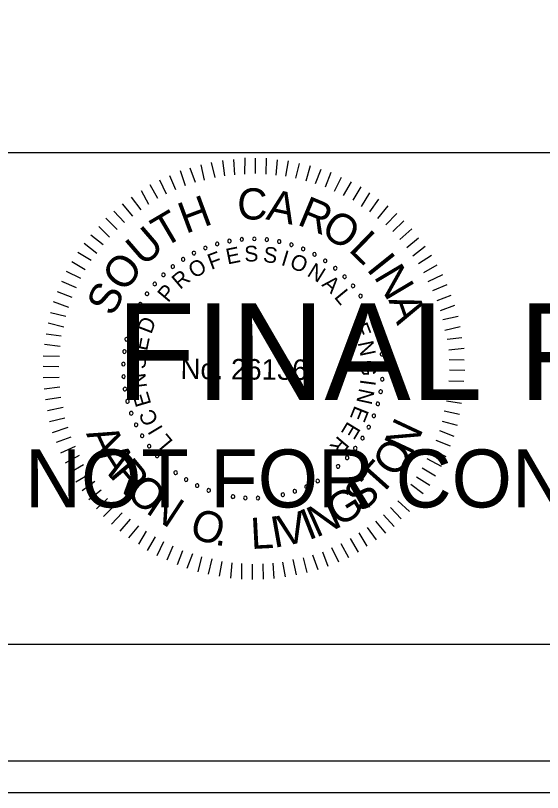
# Model space of a CAD drawing. Extents: x 967 to 1326, y 964 to 1744.
# Drawn here: x 1170.56 to 1189.3, y 1243.72 to 1271.36 of the extents above; entities that cross this region are included whole.
import ezdxf

# ---------------------------------------------------------------- set-up
doc = ezdxf.new("R2010")
doc.units = 0
for name, color, linetype in [('RD_PD_PaveShd', 7, 'Continuous'), ('RD_XS_Base', 7, 'Continuous'), ('RD_XS_CurbBase', 7, 'Continuous'), ('RD_XS_TieSlope', 7, 'Continuous'), ('RD_XS_TX_TOC', 7, 'Continuous')]:
    doc.layers.add(name, color=color, linetype=linetype)

msp = doc.modelspace()

# ---------------------------------------------------------------- linework, layer by layer
at = {"layer": 'RD_PD_PaveShd'}
for p, q in [((996.114, 1266.486), (1323.886, 1266.486)), ((1323.886, 1248.983), (996.114, 1248.983))]:
    msp.add_line(p, q, dxfattribs=at)
at = {"layer": 'RD_XS_CurbBase'}
msp.add_lwpolyline([(967.409, 1243.72), (1326.285, 1243.72), (1326.285, 1463.72), (967.409, 1463.72)], close=True, dxfattribs=at)
at = {"layer": 'RD_XS_TieSlope'}
for p, q in [((1178.01, 1265.663), (1177.93, 1266.209)), ((1178.364, 1265.699), (1178.33, 1266.244)), ((1178.717, 1265.719), (1178.722, 1266.295)), ((1179.093, 1265.739), (1179.098, 1266.292)), ((1179.469, 1265.713), (1179.489, 1266.288)), ((1179.829, 1265.687), (1179.872, 1266.231)), ((1180.174, 1265.646), (1180.271, 1266.19)), ((1176.964, 1265.419), (1176.769, 1265.935)), ((1177.287, 1265.508), (1177.169, 1266.054)), ((1177.657, 1265.597), (1177.53, 1266.128)), ((1180.535, 1265.573), (1180.662, 1266.102)), ((1180.902, 1265.478), (1181.045, 1266.022)), ((1176.264, 1265.156), (1176.053, 1265.657)), ((1176.61, 1265.306), (1176.423, 1265.83)), ((1181.231, 1265.384), (1181.428, 1265.896)), ((1181.584, 1265.265), (1181.78, 1265.786)), ((1175.933, 1265.005), (1175.699, 1265.506)), ((1181.905, 1265.109), (1182.154, 1265.606)), ((1182.226, 1264.953), (1182.506, 1265.45)), ((1175.308, 1264.634), (1175.036, 1265.12)), ((1175.624, 1264.846), (1175.352, 1265.332)), ((1182.562, 1264.789), (1182.85, 1265.27)), ((1175.03, 1264.445), (1174.681, 1264.9)), ((1182.86, 1264.572), (1183.163, 1265.053)), ((1183.158, 1264.378), (1183.484, 1264.828)), ((1174.729, 1264.217), (1174.372, 1264.665)), ((1183.447, 1264.145), (1183.811, 1264.587)), ((1174.435, 1263.997), (1174.062, 1264.399)), ((1183.729, 1263.92), (1184.116, 1264.316)), ((1174.172, 1263.753), (1173.776, 1264.148)), ((1183.98, 1263.672), (1184.368, 1264.061)), ((1173.909, 1263.479), (1173.52, 1263.858)), ((1184.232, 1263.394), (1184.657, 1263.767)), ((1173.684, 1263.197), (1173.242, 1263.546)), ((1184.475, 1263.108), (1184.892, 1263.45)), ((1173.451, 1262.9), (1173.009, 1263.256)), ((1184.687, 1262.807), (1185.128, 1263.156)), ((1173.257, 1262.64), (1172.776, 1262.936)), ((1173.039, 1262.312), (1172.559, 1262.6)), ((1184.885, 1262.544), (1185.355, 1262.832)), ((1185.081, 1262.213), (1185.56, 1262.493)), ((1172.883, 1262.006), (1172.379, 1262.256)), ((1185.24, 1261.904), (1185.756, 1262.145)), ((1172.727, 1261.677), (1172.215, 1261.904)), ((1185.399, 1261.573), (1185.907, 1261.791)), ((1172.571, 1261.333), (1172.051, 1261.53)), ((1185.549, 1261.226), (1186.057, 1261.414)), ((1172.461, 1260.974), (1171.91, 1261.178)), ((1185.669, 1260.865), (1186.185, 1261.06)), ((1172.351, 1260.652), (1171.807, 1260.787)), ((1185.759, 1260.541), (1186.297, 1260.667)), ((1172.286, 1260.276), (1171.727, 1260.419)), ((1185.832, 1260.165), (1186.371, 1260.298)), ((1172.191, 1259.955), (1171.647, 1260.029)), ((1185.906, 1259.842), (1186.436, 1259.906)), ((1172.15, 1259.587), (1171.598, 1259.653)), ((1185.964, 1259.473), (1186.51, 1259.53)), ((1172.124, 1259.234), (1171.548, 1259.239)), ((1185.977, 1259.12), (1186.514, 1259.115)), ((1172.105, 1258.866), (1171.545, 1258.871)), ((1185.997, 1258.751), (1186.542, 1258.747)), ((1172.118, 1258.482), (1171.542, 1258.471)), ((1185.971, 1258.368), (1186.508, 1258.348)), ((1172.138, 1258.136), (1171.585, 1258.072)), ((1185.952, 1258.022), (1186.497, 1257.949)), ((1172.173, 1257.768), (1171.627, 1257.688)), ((1185.888, 1257.655), (1186.417, 1257.566)), ((1172.262, 1257.414), (1171.701, 1257.296)), ((1185.808, 1257.302), (1186.345, 1257.175)), ((1172.321, 1257.037), (1171.774, 1256.911)), ((1185.729, 1256.926), (1186.265, 1256.792)), ((1172.425, 1256.707), (1171.871, 1256.519)), ((1185.634, 1256.597), (1186.146, 1256.401)), ((1172.53, 1256.36), (1172.007, 1256.173)), ((1185.508, 1256.253), (1186.013, 1256.057)), ((1172.681, 1256.029), (1172.165, 1255.788)), ((1172.831, 1255.705), (1172.323, 1255.441)), ((1185.352, 1255.924), (1185.857, 1255.675)), ((1185.188, 1255.603), (1185.7, 1255.33)), ((1172.982, 1255.374), (1172.497, 1255.094)), ((1185.024, 1255.274), (1185.498, 1254.987)), ((1173.194, 1255.042), (1172.709, 1254.762)), ((1184.822, 1254.946), (1185.288, 1254.658)), ((1173.384, 1254.78), (1172.936, 1254.453)), ((1184.62, 1254.687), (1185.055, 1254.353)), ((1173.612, 1254.478), (1173.164, 1254.129)), ((1184.403, 1254.389), (1184.814, 1254.033)), ((1173.832, 1254.177), (1173.437, 1253.812)), ((1184.155, 1254.092), (1184.574, 1253.72)), ((1174.091, 1253.945), (1173.689, 1253.541)), ((1183.899, 1253.864), (1184.28, 1253.454)), ((1174.35, 1253.674), (1173.97, 1253.263)), ((1183.644, 1253.597), (1184.024, 1253.18)), ((1174.64, 1253.442), (1174.275, 1253.022)), ((1174.937, 1253.209), (1174.58, 1252.782)), ((1183.358, 1253.37), (1183.715, 1252.944)), ((1175.212, 1253.014), (1174.932, 1252.549)), ((1182.764, 1252.952), (1183.059, 1252.482)), ((1183.065, 1253.141), (1183.384, 1252.709)), ((1175.525, 1252.812), (1175.245, 1252.331)), ((1182.463, 1252.755), (1182.743, 1252.269)), ((1175.83, 1252.633), (1175.588, 1252.136)), ((1176.159, 1252.477), (1175.94, 1251.98)), ((1181.8, 1252.431), (1182.041, 1251.93)), ((1182.124, 1252.581), (1182.396, 1252.08)), ((1176.503, 1252.321), (1176.307, 1251.816)), ((1176.855, 1252.211), (1176.651, 1251.69)), ((1177.177, 1252.1), (1177.05, 1251.572)), ((1181.122, 1252.175), (1181.31, 1251.652)), ((1181.476, 1252.28), (1181.664, 1251.771)), ((1177.545, 1252.036), (1177.409, 1251.484)), ((1177.897, 1251.933), (1177.808, 1251.412)), ((1178.25, 1251.892), (1178.207, 1251.34)), ((1178.603, 1251.866), (1178.598, 1251.313)), ((1178.978, 1251.84), (1178.974, 1251.295)), ((1179.355, 1251.86), (1179.365, 1251.307)), ((1179.715, 1251.88), (1179.749, 1251.327)), ((1180.061, 1251.915), (1180.149, 1251.393)), ((1180.423, 1252.012), (1180.541, 1251.458)), ((1180.791, 1252.07), (1180.926, 1251.54))]:
    msp.add_line(p, q, dxfattribs=at)
for centre, start, end in [((1178.609, 1263.397), 5.0653, 185.0653), ((1179.055, 1263.414), 359.5268, 179.5268), ((1179.055, 1263.414), 179.5268, 359.5268), ((1179.5, 1263.388), 353.9884, 173.9884), ((1177.312, 1263.091), 21.6807, 201.6807), ((1177.734, 1263.235), 16.1422, 196.1422), ((1177.734, 1263.235), 196.1422, 16.1422), ((1178.168, 1263.337), 10.6038, 190.6038), ((1178.168, 1263.337), 190.6038, 10.6038), ((1178.609, 1263.397), 185.0653, 5.0653), ((1179.5, 1263.388), 173.9884, 353.9884), ((1179.94, 1263.319), 168.4499, 348.4499), ((1179.94, 1263.319), 348.4499, 168.4499), ((1180.372, 1263.208), 162.9114, 342.9114), ((1180.372, 1263.208), 342.9114, 162.9114), ((1176.906, 1262.908), 27.2191, 207.2191), ((1176.906, 1262.908), 207.2191, 27.2191), ((1177.312, 1263.091), 201.6807, 21.6807), ((1180.79, 1263.056), 157.373, 337.373), ((1180.79, 1263.056), 337.373, 157.373), ((1181.193, 1262.864), 151.8345, 331.8345), ((1181.193, 1262.864), 331.8345, 151.8345), ((1176.52, 1262.686), 32.7576, 212.7576), ((1176.52, 1262.686), 212.7576, 32.7576), ((1181.574, 1262.634), 146.2961, 326.2961), ((1181.574, 1262.634), 326.2961, 146.2961), ((1176.156, 1262.428), 38.2961, 218.2961), ((1176.156, 1262.428), 218.2961, 38.2961), ((1181.932, 1262.368), 140.7576, 320.7576), ((1181.932, 1262.368), 320.7576, 140.7576), ((1175.82, 1262.135), 43.8345, 223.8345), ((1175.82, 1262.135), 223.8345, 43.8345), ((1182.263, 1262.069), 135.2191, 315.2191), ((1182.263, 1262.069), 315.2191, 135.2191), ((1175.513, 1261.812), 49.373, 229.373), ((1175.513, 1261.812), 229.373, 49.373), ((1182.563, 1261.74), 129.6807, 309.6807), ((1182.563, 1261.74), 309.6807, 129.6807), ((1175.239, 1261.461), 54.9114, 234.9114), ((1175.239, 1261.461), 234.9114, 54.9114), ((1182.83, 1261.383), 124.1422, 304.1422), ((1182.83, 1261.383), 304.1422, 124.1422), ((1175, 1261.085), 60.4499, 240.4499), ((1175, 1261.085), 240.4499, 60.4499), ((1183.061, 1261.002), 118.6038, 298.6038), ((1183.061, 1261.002), 298.6038, 118.6038), ((1174.798, 1260.687), 65.9884, 245.9884), ((1174.798, 1260.687), 245.9884, 65.9884), ((1183.255, 1260.601), 113.0653, 293.0653), ((1183.255, 1260.601), 293.0653, 113.0653), ((1174.636, 1260.272), 71.5268, 251.5268), ((1174.636, 1260.272), 251.5268, 71.5268), ((1183.408, 1260.182), 107.5268, 287.5268), ((1183.408, 1260.182), 287.5268, 107.5268), ((1174.514, 1259.843), 77.0653, 257.0653), ((1174.514, 1259.843), 257.0653, 77.0653), ((1183.521, 1259.751), 101.9884, 281.9884), ((1183.521, 1259.751), 281.9884, 101.9884), ((1174.435, 1259.405), 82.6038, 262.6038), ((1174.435, 1259.405), 262.6038, 82.6038), ((1183.592, 1259.311), 96.4499, 276.4499), ((1183.592, 1259.311), 276.4499, 96.4499), ((1174.398, 1258.961), 88.1422, 268.1422), ((1174.398, 1258.961), 268.1422, 88.1422), ((1183.619, 1258.866), 90.9114, 270.9114), ((1183.619, 1258.866), 270.9114, 90.9114), ((1174.404, 1258.515), 93.6807, 273.6807), ((1174.404, 1258.515), 273.6807, 93.6807), ((1183.604, 1258.421), 85.373, 265.373), ((1183.604, 1258.421), 265.373, 85.373), ((1174.453, 1258.072), 99.2191, 279.2191), ((1174.453, 1258.072), 279.2191, 99.2191), ((1183.546, 1257.979), 79.8345, 259.8345), ((1183.546, 1257.979), 259.8345, 79.8345), ((1174.545, 1257.636), 104.7576, 284.7576), ((1174.545, 1257.636), 284.7576, 104.7576), ((1183.445, 1257.545), 74.2961, 254.2961), ((1183.445, 1257.545), 254.2961, 74.2961), ((1174.678, 1257.211), 110.2961, 290.2961), ((1174.678, 1257.211), 290.2961, 110.2961), ((1183.303, 1257.122), 68.7576, 248.7576), ((1183.303, 1257.122), 248.7576, 68.7576), ((1174.852, 1256.8), 115.8345, 295.8345), ((1174.852, 1256.8), 295.8345, 115.8345), ((1183.121, 1256.716), 63.2191, 243.2191), ((1183.121, 1256.716), 243.2191, 63.2191), ((1175.065, 1256.409), 121.373, 301.373), ((1175.065, 1256.409), 301.373, 121.373), ((1182.9, 1256.328), 57.6807, 237.6807), ((1182.9, 1256.328), 237.6807, 57.6807), ((1175.314, 1256.039), 126.9114, 306.9114), ((1175.314, 1256.039), 306.9114, 126.9114), ((1182.643, 1255.964), 52.1422, 232.1422), ((1182.643, 1255.964), 232.1422, 52.1422), ((1175.598, 1255.696), 132.4499, 312.4499), ((1175.598, 1255.696), 312.4499, 132.4499), ((1182.353, 1255.627), 46.6038, 226.6038), ((1175.914, 1255.381), 137.9884, 317.9884), ((1175.914, 1255.381), 317.9884, 137.9884), ((1182.353, 1255.627), 226.6038, 46.6038), ((1176.258, 1255.099), 143.5268, 323.5268), ((1176.258, 1255.099), 323.5268, 143.5268), ((1182.03, 1255.319), 41.0653, 221.0653), ((1182.03, 1255.319), 221.0653, 41.0653), ((1176.629, 1254.851), 149.0653, 329.0653), ((1176.629, 1254.851), 329.0653, 149.0653), ((1181.305, 1254.803), 29.9884, 209.9884), ((1181.68, 1255.043), 35.5268, 215.5268), ((1181.68, 1255.043), 215.5268, 35.5268), ((1177.021, 1254.639), 154.6038, 334.6038), ((1177.021, 1254.639), 334.6038, 154.6038), ((1180.908, 1254.6), 24.4499, 204.4499), ((1180.908, 1254.6), 204.4499, 24.4499), ((1181.305, 1254.803), 209.9884, 29.9884), ((1177.432, 1254.467), 160.1422, 340.1422), ((1177.432, 1254.467), 340.1422, 160.1422), ((1177.858, 1254.335), 165.6807, 345.6807), ((1177.858, 1254.335), 345.6807, 165.6807), ((1178.294, 1254.245), 351.2191, 171.2191), ((1179.627, 1254.232), 7.8345, 187.8345), ((1180.065, 1254.313), 13.373, 193.373), ((1180.065, 1254.313), 193.373, 13.373), ((1180.494, 1254.436), 18.9114, 198.9114), ((1180.494, 1254.436), 198.9114, 18.9114), ((1178.294, 1254.245), 171.2191, 351.2191), ((1178.737, 1254.198), 356.7576, 176.7576), ((1178.737, 1254.198), 176.7576, 356.7576), ((1179.183, 1254.193), 2.2961, 182.2961), ((1179.183, 1254.193), 182.2961, 2.2961), ((1179.627, 1254.232), 187.8345, 7.8345)]:
    msp.add_arc(centre, 0.0627, start, end, dxfattribs=at)
at = {"layer": 'RD_XS_TX_TOC'}
for points in [[(967.409, 1243.72), (1326.285, 1243.72), (1326.285, 1463.72), (967.409, 1463.72)], [(988.525, 1244.84), (1326.285, 1244.84), (1326.285, 1462.6), (988.525, 1462.6)]]:
    msp.add_lwpolyline(points, close=True, dxfattribs=at)

# ---------------------------------------------------------------- texts
at = {"layer": 'RD_XS_Base'}
for s, height, p in [('FINAL PLANS', 3.4375, (1174.145, 1257.685)), ('NOT FOR CONSTRUCTION', 2.0625, (1170.901, 1253.86))]:
    msp.add_text(s, height=height, dxfattribs=at).set_placement(p)
at = {"layer": 'RD_XS_TieSlope'}
for s, height, rotation, p in [('C', 1.11, 359.5482, (1178.442, 1264.108)), ('A', 1.11, 348.1981, (1179.439, 1264.115)), ('H', 1.11, 20.3637, (1176.614, 1263.587)), ('R', 1.11, 337.4344, (1180.541, 1263.937)), ('T', 1.11, 30.4992, (1175.828, 1263.072)), ('O', 1.108, 326.5869, (1181.366, 1263.609)), ('U', 1.11, 40.8022, (1175.102, 1262.403)), ('L', 1.11, 315.9488, (1182.373, 1263.003)), ('E', 0.557, 11.4103, (1178.103, 1262.503)), ('S', 0.557, 2.208, (1178.709, 1262.601)), ('S', 0.557, 352.6608, (1179.346, 1262.599)), ('F', 0.557, 20.6127, (1177.52, 1262.309)), ('I', 0.557, 343.1136, (1179.975, 1262.491)), ('O', 0.557, 338.4392, (1180.274, 1262.401)), ('I', 1.11, 308.6613, (1183.011, 1262.338)), ('O', 1.11, 52.0267, (1174.435, 1261.474)), ('O', 0.557, 30.8477, (1176.917, 1261.987)), ('N', 0.557, 328.2042, (1180.896, 1262.12)), ('N', 1.11, 300.7037, (1183.285, 1262.075)), ('R', 0.557, 40.3949, (1176.415, 1261.594)), ('A', 0.557, 318.657, (1181.424, 1261.762)), ('S', 1.108, 63.2511, (1174.029, 1260.619)), ('P', 0.557, 49.9421, (1175.985, 1261.124)), ('L', 0.557, 309.4546, (1181.869, 1261.339)), ('A', 1.11, 289.4792, (1183.814, 1261.243)), ('D', 0.557, 69.0364, (1175.386, 1260.003)), ('E', 0.557, 291.049, (1182.53, 1260.307)), ('E', 0.557, 78.2388, (1175.238, 1259.407)), ('N', 0.557, 281.8466, (1182.728, 1259.726)), ('S', 0.557, 87.786, (1175.187, 1258.772)), ('No. 26136', 0.7311, 359.5268, (1176.429, 1258.43)), ('G', 0.557, 272.2995, (1182.833, 1259.097)), ('N', 0.557, 97.3332, (1175.242, 1258.137)), ('I', 0.557, 262.4084, (1182.83, 1258.437)), ('E', 0.557, 106.5355, (1175.394, 1257.541)), ('N', 0.557, 257.7339, (1182.789, 1258.127)), ('C', 0.557, 116.4266, (1175.661, 1256.938)), ('E', 0.557, 248.1867, (1182.628, 1257.511)), ('I', 0.557, 121.1011, (1175.823, 1256.67)), ('E', 0.557, 238.9844, (1182.378, 1256.949)), ('N', 1.105, 64.8922, (1184.632, 1255.684)), ('A', 1.105, 294.7297, (1173.062, 1256.486)), ('L', 0.557, 129.9595, (1176.187, 1256.204)), ('R', 0.557, 229.782, (1182.041, 1256.435)), ('A', 1.105, 302.2892, (1173.414, 1255.72)), ('O', 1.105, 56.2059, (1184.102, 1254.874)), ('R', 1.105, 309.8487, (1173.865, 1255.007)), ('T', 1.105, 48.2685, (1183.515, 1254.211)), ('O', 1.105, 317.7861, (1174.434, 1254.33)), ('S', 1.105, 40.3311, (1182.842, 1253.636)), ('N', 1.105, 326.4725, (1175.158, 1253.686)), ('G', 1.105, 32.0198, (1182.059, 1253.14)), ('N', 1.105, 24.0824, (1181.252, 1252.776)), ('O', 1.105, 342.3472, (1176.697, 1252.82)), ('V', 1.105, 12.7741, (1180.033, 1252.457)), ('I', 1.105, 21.4605, (1180.976, 1252.681)), ('L', 1.105, 2.9677, (1178.943, 1252.379)), ('I', 1.105, 10.1523, (1179.743, 1252.418)), ('.', 1.105, 351.0336, (1177.623, 1252.536))]:
    msp.add_text(s, height=height, rotation=rotation, dxfattribs=at).set_placement(p)

doc.saveas('drawing.dxf')
